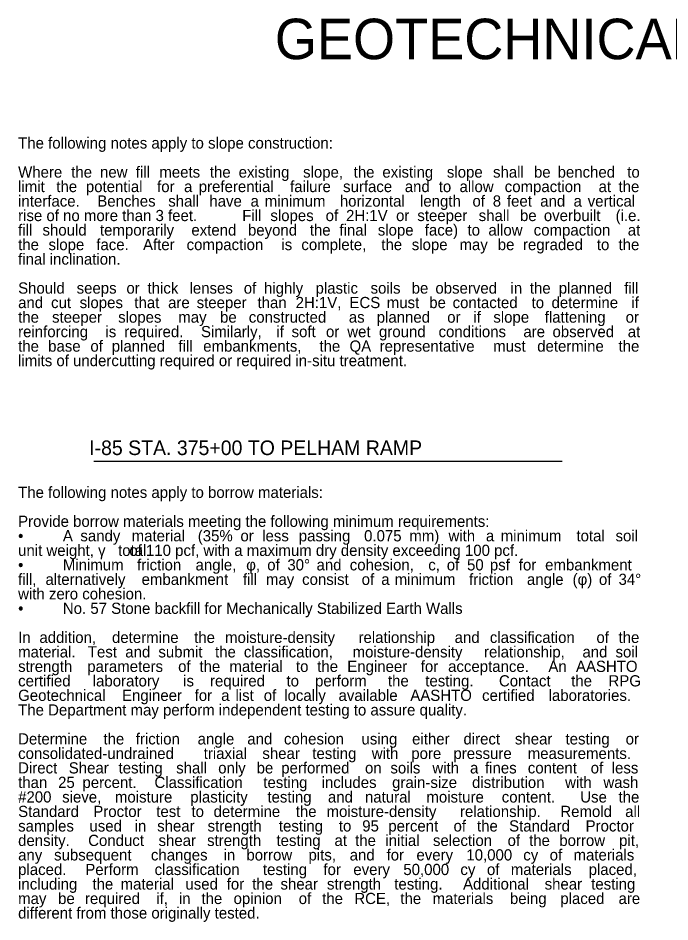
# Model space of a CAD drawing. Extents: x 4804 to 5434, y 4929 to 5221.
# Drawn here: x 5102.6 to 5183.2, y 5103.6 to 5215.2 of the extents above; entities that cross this region are included whole.
import ezdxf

# ---------------------------------------------------------------- set-up
doc = ezdxf.new("R2010")
doc.units = 0
doc.layers.add('RD_TX_RoadID', color=7, linetype='Continuous')

msp = doc.modelspace()

# ---------------------------------------------------------------- linework, layer by layer
at = {"layer": 'RD_TX_RoadID'}
msp.add_line((5111.99, 5160.49), (5169.89, 5160.49), dxfattribs=at)

# ---------------------------------------------------------------- texts
for s, height, p in [('GEOTECHNICAL NOTES', 5, (5134.37, 5210.16)), ('The following notes apply to slope construction:', 1.3845, (5102.65, 5199.12)), ('Where ', 1.384, (5102.65, 5195.53)), ('the ', 1.384, (5109.21, 5195.53)), ('new ', 1.384, (5112.77, 5195.53)), ('fill ', 1.384, (5117.19, 5195.53)), ('meets ', 1.384, (5120.1, 5195.53)), ('the ', 1.384, (5126.34, 5195.53)), ('existing ', 1.384, (5129.9, 5195.53)), ('slope, ', 1.384, (5137.86, 5195.53)), ('the ', 1.384, (5144.11, 5195.53)), ('existing ', 1.384, (5147.66, 5195.53)), ('slope ', 1.384, (5155.63, 5195.53)), ('shall ', 1.384, (5161.33, 5195.53)), ('be ', 1.384, (5166.39, 5195.53)), ('benched ', 1.384, (5169.31, 5195.53)), ('to ', 1.384, (5177.92, 5195.53)), ('limit ', 1.384, (5102.65, 5193.74)), ('the ', 1.384, (5107.37, 5193.74)), ('potential ', 1.384, (5111.02, 5193.74)), ('for ', 1.384, (5119.82, 5193.74)), ('preferential ', 1.3845, (5124.97, 5193.74)), ('failure ', 1.384, (5136.25, 5193.74)), ('surface ', 1.384, (5142.8, 5193.74)), ('and ', 1.384, (5150.43, 5193.74)), ('to ', 1.384, (5154.62, 5193.74)), ('allow ', 1.384, (5157.19, 5193.74)), ('compaction ', 1.3845, (5162.78, 5193.74)), ('at ', 1.384, (5174.38, 5193.74)), ('the ', 1.384, (5176.84, 5193.74)), ('a ', 1.384, (5123.15, 5193.74)), ('interface. ', 1.3845, (5102.65, 5191.95)), (' Benches ', 1.384, (5111.92, 5191.95)), ('shall ', 1.384, (5121.2, 5191.95)), ('have ', 1.384, (5126.28, 5191.95)), ('a ', 1.384, (5131.37, 5191.95)), ('minimum ', 1.384, (5133.12, 5191.95)), ('horizontal ', 1.3845, (5142.4, 5191.95)), ('length ', 1.384, (5152.31, 5191.95)), ('of ', 1.384, (5158.79, 5191.95)), ('8 ', 1.384, (5161.3, 5191.95)), ('feet ', 1.384, (5163.05, 5191.95)), ('and ', 1.384, (5167.16, 5191.95)), ('a ', 1.384, (5171.28, 5191.95)), ('vertical ', 1.384, (5173.03, 5191.95)), ('rise of no more than 3 feet.', 1.3845, (5102.65, 5190.16)), ('Fill ', 1.384, (5130.34, 5190.16)), ('slopes ', 1.384, (5133.82, 5190.16)), ('of ', 1.384, (5140.65, 5190.16)), ('shall ', 1.384, (5159.56, 5190.16)), ('be ', 1.384, (5164.66, 5190.16)), ('overbuilt ', 1.384, (5167.61, 5190.16)), ('(i.e. ', 1.384, (5176.48, 5190.16)), ('2H:1V ', 1.384, (5143.17, 5190.16)), ('or ', 1.384, (5149.35, 5190.16)), ('steeper ', 1.384, (5151.98, 5190.16)), ('fill ', 1.384, (5102.65, 5188.37)), ('should ', 1.384, (5105.66, 5188.37)), ('temporarily ', 1.3845, (5112.76, 5188.37)), ('extend ', 1.384, (5124.06, 5188.37)), ('beyond ', 1.384, (5131.05, 5188.37)), ('the ', 1.384, (5138.69, 5188.37)), ('final ', 1.384, (5142.35, 5188.37)), ('slope ', 1.384, (5147.09, 5188.37)), ('face) ', 1.384, (5152.9, 5188.37)), ('to ', 1.384, (5158.18, 5188.37)), ('allow ', 1.384, (5160.76, 5188.37)), ('compaction ', 1.3845, (5166.36, 5188.37)), ('at ', 1.384, (5177.98, 5188.37)), ('the ', 1.384, (5102.65, 5186.57)), ('slope ', 1.384, (5106.4, 5186.57)), ('face. ', 1.384, (5112.31, 5186.57)), (' After ', 1.384, (5117.57, 5186.57)), ('compaction ', 1.3845, (5123.47, 5186.57)), ('is ', 1.384, (5135.18, 5186.57)), ('complete, ', 1.384, (5137.65, 5186.57)), ('the ', 1.384, (5147.53, 5186.57)), ('slope ', 1.384, (5151.29, 5186.57)), ('may ', 1.384, (5157.19, 5186.57)), ('be ', 1.384, (5161.92, 5186.57)), ('regraded ', 1.384, (5165.03, 5186.57)), ('to ', 1.384, (5174.16, 5186.57)), ('the ', 1.384, (5176.84, 5186.57)), ('final inclination.', 1.3845, (5102.65, 5184.78)), ('Should ', 1.384, (5102.65, 5181.2)), ('thick ', 1.384, (5118.64, 5181.2)), ('lenses ', 1.384, (5123.83, 5181.2)), ('of ', 1.384, (5130.53, 5181.2)), ('highly ', 1.384, (5133.03, 5181.2)), ('plastic ', 1.384, (5139.4, 5181.2)), ('soils ', 1.384, (5146.2, 5181.2)), ('be ', 1.384, (5151.28, 5181.2)), ('observed ', 1.384, (5154.21, 5181.2)), ('in ', 1.384, (5163.49, 5181.2)), ('the ', 1.384, (5165.88, 5181.2)), ('planned ', 1.384, (5169.46, 5181.2)), ('fill ', 1.384, (5177.55, 5181.2)), ('seeps ', 1.384, (5109.88, 5181.2)), ('or ', 1.384, (5116.03, 5181.2)), ('and ', 1.384, (5102.65, 5179.41)), ('cut ', 1.384, (5106.72, 5179.41)), ('slopes ', 1.384, (5110.25, 5179.41)), ('that ', 1.384, (5117.01, 5179.41)), ('are ', 1.384, (5121.18, 5179.41)), ('steeper ', 1.384, (5124.71, 5179.41)), ('than ', 1.384, (5132.23, 5179.41)), ('2H:1V, ', 1.384, (5136.94, 5179.41)), ('ECS ', 1.384, (5143.59, 5179.41)), ('must ', 1.384, (5148.2, 5179.41)), ('be ', 1.384, (5153.45, 5179.41)), ('contacted ', 1.384, (5156.34, 5179.41)), ('to ', 1.384, (5166.1, 5179.41)), ('determine ', 1.384, (5168.56, 5179.41)), ('if ', 1.384, (5178.43, 5179.41)), ('the ', 1.384, (5102.65, 5177.61)), ('steeper ', 1.384, (5106.84, 5177.61)), ('slopes ', 1.384, (5115.01, 5177.61)), ('may ', 1.384, (5122.44, 5177.61)), ('be ', 1.384, (5127.6, 5177.61)), ('constructed ', 1.3845, (5131.15, 5177.61)), ('as ', 1.384, (5143.51, 5177.61)), ('planned ', 1.384, (5146.96, 5177.61)), ('or ', 1.384, (5155.67, 5177.61)), ('if ', 1.384, (5158.9, 5177.61)), ('slope ', 1.384, (5161.37, 5177.61)), ('flattening ', 1.3845, (5167.72, 5177.61)), ('or ', 1.384, (5177.72, 5177.61)), ('reinforcing ', 1.3845, (5102.65, 5175.82)), ('is ', 1.384, (5113.44, 5175.82)), ('required. ', 1.384, (5115.76, 5175.82)), (' Similarly, ', 1.3845, (5124.73, 5175.82)), ('if ', 1.384, (5134.56, 5175.82)), ('soft ', 1.384, (5136.44, 5175.82)), ('wet ', 1.384, (5143.32, 5175.82)), ('ground ', 1.384, (5147.24, 5175.82)), ('conditions ', 1.3845, (5154.6, 5175.82)), ('observed ', 1.384, (5168.68, 5175.82)), ('at ', 1.384, (5177.98, 5175.82)), ('or ', 1.384, (5140.69, 5175.82)), ('are ', 1.384, (5165.08, 5175.82)), ('the ', 1.384, (5102.65, 5174.03)), ('base ', 1.384, (5106.36, 5174.03)), ('of ', 1.384, (5111.58, 5174.03)), ('planned ', 1.384, (5114.22, 5174.03)), ('fill ', 1.384, (5122.45, 5174.03)), ('embankments, ', 1.3845, (5125.52, 5174.03)), ('the ', 1.384, (5139.88, 5174.03)), ('QA ', 1.384, (5143.6, 5174.03)), ('representative ', 1.3845, (5147.32, 5174.03)), ('must ', 1.384, (5161.35, 5174.03)), ('determine ', 1.384, (5166.79, 5174.03)), ('the ', 1.384, (5176.84, 5174.03)), ('limits of undercutting required or required in-situ treatment.', 1.3845, (5102.65, 5172.24)), ('I-85 STA. 375+00 TO PELHAM RAMP', 1.8, (5111.43, 5161.26)), ('The following notes apply to borrow materials:', 1.3845, (5102.65, 5155.97)), ('Provide borrow materials meeting the following minimum requirements:', 1.3845, (5102.65, 5152.39)), ('•', 1.38, (5102.65, 5150.6)), ('A ', 1.384, (5108.18, 5150.6)), ('sandy ', 1.384, (5110.34, 5150.6)), ('material ', 1.384, (5116.68, 5150.6)), ('(35% ', 1.384, (5124.85, 5150.6)), ('or ', 1.384, (5130.12, 5150.6)), ('less ', 1.384, (5132.81, 5150.6)), ('passing ', 1.384, (5137.33, 5150.6)), ('0.075 ', 1.384, (5145.4, 5150.6)), ('mm) ', 1.384, (5150.99, 5150.6)), ('with ', 1.384, (5155.83, 5150.6)), ('a ', 1.384, (5160.45, 5150.6)), ('minimum ', 1.384, (5162.28, 5150.6)), ('total ', 1.384, (5171.64, 5150.6)), ('soil ', 1.384, (5176.47, 5150.6)), ('unit weight, γ', 1.3845, (5102.65, 5148.8)), ('total ', 1.384, (5115, 5148.8)), ('of 110 pcf, with a maximum dry density exceeding 100 pcf. ', 1.3845, (5116.39, 5148.8)), ('Minimum ', 1.384, (5108.18, 5147.01)), ('friction ', 1.384, (5117.35, 5147.01)), ('angle, ', 1.384, (5124.57, 5147.01)), ('φ, ', 1.384, (5130.83, 5147.01)), ('of ', 1.384, (5133.43, 5147.01)), ('30° ', 1.384, (5135.92, 5147.01)), ('and ', 1.384, (5139.52, 5147.01)), ('cohesion, ', 1.384, (5143.63, 5147.01)), ('c, ', 1.384, (5153.33, 5147.01)), ('of ', 1.384, (5155.62, 5147.01)), ('50 ', 1.384, (5158.12, 5147.01)), ('psf ', 1.384, (5160.94, 5147.01)), ('for ', 1.384, (5164.52, 5147.01)), ('embankment ', 1.3845, (5167.77, 5147.01)), ('•', 1.38, (5102.65, 5147.01)), ('fill, ', 1.384, (5102.65, 5145.22)), ('alternatively ', 1.3845, (5106.03, 5145.22)), ('embankment ', 1.3845, (5117.91, 5145.22)), ('fill ', 1.384, (5130.43, 5145.22)), ('may ', 1.384, (5133.27, 5145.22)), ('consist ', 1.384, (5137.74, 5145.22)), ('of ', 1.384, (5145.1, 5145.22)), ('a ', 1.384, (5147.52, 5145.22)), ('minimum ', 1.384, (5149.18, 5145.22)), ('friction ', 1.384, (5158.37, 5145.22)), ('angle ', 1.384, (5165.52, 5145.22)), ('(φ) ', 1.384, (5171.16, 5145.22)), ('of ', 1.384, (5174.42, 5145.22)), ('34° ', 1.384, (5176.84, 5145.22)), ('with zero cohesion.', 1.3845, (5102.65, 5143.43)), ('•', 1.38, (5102.65, 5141.64)), ('No. 57 Stone backfill for Mechanically Stabilized Earth Walls', 1.3845, (5108.18, 5141.64)), ('In ', 1.384, (5102.65, 5138.05)), ('addition, ', 1.384, (5105.28, 5138.05)), ('determine ', 1.384, (5114.25, 5138.05)), ('the ', 1.384, (5124.4, 5138.05)), ('moisture-density ', 1.3845, (5128.22, 5138.05)), ('relationship ', 1.3845, (5144.71, 5138.05)), ('and ', 1.384, (5156.59, 5138.05)), ('classification ', 1.3845, (5160.94, 5138.05)), ('of ', 1.384, (5174.11, 5138.05)), ('the ', 1.384, (5176.84, 5138.05)), ('material. ', 1.384, (5102.65, 5136.26)), ('Test ', 1.384, (5111.26, 5136.26)), ('and ', 1.384, (5115.89, 5136.26)), ('submit ', 1.384, (5119.98, 5136.26)), ('the ', 1.384, (5126.98, 5136.26)), ('classification, ', 1.3845, (5130.54, 5136.26)), ('moisture-density ', 1.3845, (5143.98, 5136.26)), ('relationship, ', 1.3845, (5160.22, 5136.26)), ('and ', 1.384, (5172.38, 5136.26)), ('soil ', 1.384, (5176.47, 5136.26)), ('strength ', 1.384, (5102.65, 5134.47)), ('parameters ', 1.3845, (5111.19, 5134.47)), ('of ', 1.384, (5122.42, 5134.47)), ('the ', 1.384, (5125.05, 5134.47)), ('material ', 1.384, (5128.76, 5134.47)), ('to ', 1.384, (5136.98, 5134.47)), ('the ', 1.384, (5139.61, 5134.47)), ('Engineer ', 1.384, (5143.32, 5134.47)), ('for ', 1.384, (5152.4, 5134.47)), ('acceptance. ', 1.3845, (5155.78, 5134.47)), (' An ', 1.384, (5167.66, 5134.47)), ('AASHTO ', 1.384, (5171.58, 5134.47)), ('certified ', 1.384, (5102.65, 5132.68)), ('laboratory ', 1.3845, (5111.87, 5132.68)), ('is ', 1.384, (5123.04, 5132.68)), ('required ', 1.384, (5126.36, 5132.68)), ('to ', 1.384, (5135.81, 5132.68)), ('perform ', 1.384, (5139.34, 5132.68)), ('the ', 1.384, (5148.35, 5132.68)), ('testing. ', 1.384, (5152.96, 5132.68)), (' Contact ', 1.384, (5161.55, 5132.68)), ('the ', 1.384, (5170.99, 5132.68)), ('RPG ', 1.384, (5175.6, 5132.68)), ('Geotechnical ', 1.3845, (5102.65, 5130.89)), ('Engineer ', 1.384, (5115.49, 5130.89)), ('for ', 1.384, (5124.46, 5130.89)), ('a ', 1.384, (5127.74, 5130.89)), ('list ', 1.384, (5129.51, 5130.89)), ('of ', 1.384, (5133, 5130.89)), ('locally ', 1.384, (5135.53, 5130.89)), ('available ', 1.384, (5142.24, 5130.89)), ('AASHTO ', 1.384, (5151.11, 5130.89)), ('certified ', 1.384, (5159.98, 5130.89)), ('laboratories. ', 1.3845, (5168.2, 5130.89)), ('The Department may perform independent testing to assure quality. ', 1.3845, (5102.65, 5129.09)), ('Determine ', 1.384, (5102.65, 5125.51)), ('the ', 1.384, (5113.19, 5125.51)), ('friction ', 1.384, (5117.18, 5125.51)), ('angle ', 1.384, (5124.83, 5125.51)), ('and ', 1.384, (5130.97, 5125.51)), ('cohesion ', 1.384, (5135.5, 5125.51)), ('using ', 1.384, (5145.08, 5125.51)), ('either ', 1.384, (5151.33, 5125.51)), ('direct ', 1.384, (5157.68, 5125.51)), ('shear ', 1.384, (5164.04, 5125.51)), ('testing ', 1.384, (5170.29, 5125.51)), ('or ', 1.384, (5177.72, 5125.51)), ('consolidated-undrained ', 1.3845, (5102.65, 5123.72)), ('triaxial ', 1.384, (5125.58, 5123.72)), ('shear ', 1.384, (5132.83, 5123.72)), ('testing ', 1.384, (5139, 5123.72)), ('with ', 1.384, (5146.35, 5123.72)), ('pore ', 1.384, (5151.23, 5123.72)), ('pressure ', 1.384, (5156.44, 5123.72)), ('measurements. ', 1.3845, (5165.62, 5123.72)), ('Direct ', 1.384, (5102.65, 5121.93)), ('Shear ', 1.384, (5108.91, 5121.93)), ('testing ', 1.384, (5115.06, 5121.93)), ('shall ', 1.384, (5122.18, 5121.93)), ('only ', 1.384, (5127.37, 5121.93)), ('be ', 1.384, (5132.12, 5121.93)), ('performed ', 1.384, (5135.16, 5121.93)), ('on ', 1.384, (5145.51, 5121.93)), ('soils ', 1.384, (5148.65, 5121.93)), ('with ', 1.384, (5153.84, 5121.93)), ('a ', 1.384, (5158.49, 5121.93)), ('fines ', 1.384, (5160.34, 5121.93)), ('content ', 1.384, (5165.63, 5121.93)), ('of ', 1.384, (5173.4, 5121.93)), ('less ', 1.384, (5176, 5121.93)), ('than ', 1.384, (5102.65, 5120.14)), ('25 ', 1.384, (5107.59, 5120.14)), ('percent. ', 1.384, (5110.6, 5120.14)), (' Classification ', 1.3845, (5118.98, 5120.14)), ('testing ', 1.384, (5132.95, 5120.14)), ('includes ', 1.384, (5140.15, 5120.14)), ('grain-size ', 1.3845, (5148.86, 5120.14)), ('distribution ', 1.3845, (5158.74, 5120.14)), ('with ', 1.384, (5170.24, 5120.14)), ('wash ', 1.384, (5174.97, 5120.14)), ('#200 ', 1.384, (5102.65, 5118.34)), ('sieve, ', 1.384, (5108.09, 5118.34)), ('moisture ', 1.384, (5114.61, 5118.34)), ('plasticity ', 1.3845, (5123.92, 5118.34)), ('testing ', 1.384, (5133.45, 5118.34)), ('and ', 1.384, (5140.93, 5118.34)), ('natural ', 1.384, (5145.51, 5118.34)), ('moisture ', 1.384, (5153.1, 5118.34)), ('content. ', 1.384, (5162.41, 5118.34)), ('  Use ', 1.384, (5171.08, 5118.34)), ('the ', 1.384, (5176.84, 5118.34)), ('Standard ', 1.384, (5102.65, 5116.55)), ('Proctor ', 1.384, (5111.94, 5116.55)), ('determine ', 1.384, (5126.8, 5116.55)), ('the ', 1.384, (5136.95, 5116.55)), ('moisture-density ', 1.3845, (5140.76, 5116.55)), ('relationship. ', 1.3845, (5157.25, 5116.55)), ('Remold ', 1.384, (5169.65, 5116.55)), ('all ', 1.384, (5177.66, 5116.55)), ('test ', 1.384, (5119.72, 5116.55)), ('to ', 1.384, (5124.07, 5116.55)), ('samples ', 1.384, (5102.65, 5114.76)), ('used ', 1.384, (5111.46, 5114.76)), ('in ', 1.384, (5117.04, 5114.76)), ('shear ', 1.384, (5119.83, 5114.76)), ('strength ', 1.384, (5126.06, 5114.76)), ('testing ', 1.384, (5134.87, 5114.76)), ('to ', 1.384, (5142.28, 5114.76)), ('95 ', 1.384, (5145.17, 5114.76)), ('percent ', 1.384, (5148.39, 5114.76)), ('of ', 1.384, (5156.45, 5114.76)), ('the ', 1.384, (5159.35, 5114.76)), ('Standard ', 1.384, (5163.32, 5114.76)), ('Proctor ', 1.384, (5172.77, 5114.76)), ('density. ', 1.384, (5102.65, 5112.97)), (' Conduct ', 1.384, (5110.79, 5112.97)), ('shear ', 1.384, (5120, 5112.97)), ('strength ', 1.384, (5126, 5112.97)), ('testing ', 1.384, (5134.57, 5112.97)), ('at ', 1.384, (5141.74, 5112.97)), ('the ', 1.384, (5144.29, 5112.97)), ('initial ', 1.384, (5148.03, 5112.97)), ('selection ', 1.384, (5153.91, 5112.97)), ('of ', 1.384, (5163.13, 5112.97)), ('the ', 1.384, (5165.79, 5112.97)), ('borrow ', 1.384, (5169.52, 5112.97)), ('pit, ', 1.384, (5176.91, 5112.97)), ('subsequent ', 1.3845, (5107.09, 5111.18)), ('changes ', 1.384, (5119.06, 5111.18)), ('in ', 1.384, (5128.03, 5111.18)), ('borrow ', 1.384, (5130.86, 5111.18)), ('pits, ', 1.384, (5138.53, 5111.18)), ('and ', 1.384, (5143.62, 5111.18)), ('for ', 1.384, (5148.18, 5111.18)), ('10,000 ', 1.384, (5158.04, 5111.18)), ('of ', 1.384, (5168.33, 5111.18)), ('materials ', 1.384, (5171.28, 5111.18)), ('any ', 1.384, (5102.65, 5111.18)), ('every ', 1.384, (5151.87, 5111.18)), ('cy ', 1.384, (5165.07, 5111.18)), ('placed. ', 1.384, (5102.65, 5109.38)), (' Perform ', 1.384, (5110.44, 5109.38)), ('classification ', 1.3845, (5119.52, 5109.38)), ('testing ', 1.384, (5132.9, 5109.38)), ('for ', 1.384, (5140.37, 5109.38)), ('every ', 1.384, (5144.07, 5109.38)), ('50,000 ', 1.384, (5150.25, 5109.38)), ('cy ', 1.384, (5157.3, 5109.38)), ('of ', 1.384, (5160.58, 5109.38)), ('materials ', 1.384, (5163.53, 5109.38)), ('placed, ', 1.384, (5173.15, 5109.38)), ('including ', 1.384, (5102.65, 5107.59)), ('the ', 1.384, (5111.83, 5107.59)), ('material ', 1.384, (5115.31, 5107.59)), ('used ', 1.384, (5123.32, 5107.59)), ('for ', 1.384, (5128.42, 5107.59)), ('the ', 1.384, (5131.58, 5107.59)), ('shear ', 1.384, (5135.07, 5107.59)), ('strength ', 1.384, (5140.81, 5107.59)), ('testing. ', 1.384, (5149.13, 5107.59)), ('  Additional ', 1.3845, (5156.6, 5107.59)), ('shear ', 1.384, (5167.71, 5107.59)), ('testing ', 1.384, (5173.46, 5107.59)), ('may ', 1.384, (5102.65, 5105.8)), ('be ', 1.384, (5107.59, 5105.8)), ('required ', 1.384, (5110.91, 5105.8)), ('if, ', 1.384, (5119.72, 5105.8)), ('in ', 1.384, (5122.51, 5105.8)), ('the ', 1.384, (5125.3, 5105.8)), ('opinion ', 1.384, (5129.27, 5105.8)), ('of ', 1.384, (5137.32, 5105.8)), ('the ', 1.384, (5140.22, 5105.8)), ('RCE, ', 1.384, (5144.19, 5105.8)), ('the ', 1.384, (5149.88, 5105.8)), ('materials ', 1.384, (5153.86, 5105.8)), ('being ', 1.384, (5163.42, 5105.8)), ('placed ', 1.384, (5169.65, 5105.8)), ('are ', 1.384, (5176.84, 5105.8)), ('different from those originally tested. ', 1.3845, (5102.65, 5104.01))]:
    msp.add_text(s, height=height, dxfattribs=at).set_placement(p)

doc.saveas('drawing.dxf')
